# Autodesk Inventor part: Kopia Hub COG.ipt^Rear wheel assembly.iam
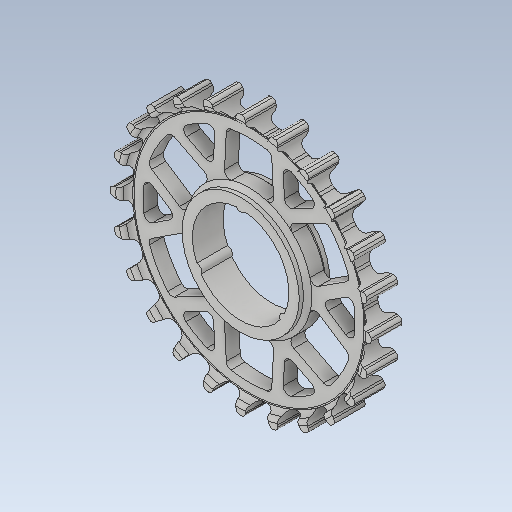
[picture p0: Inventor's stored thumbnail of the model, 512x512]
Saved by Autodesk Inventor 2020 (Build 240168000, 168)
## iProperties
Created: 2017-09
Part Number: Kopia Hub COG.ipt^Rear wheel assembly.iam
Material: Ogólny
Document SubType Name: Modeling
Designer: Tomasz
Density: 1 g/cm^3
Appearance: Domyślna
Sending System: SolidWorks 2017
Last Author: Tomasz
Last Saved: 2017-09-11
Author: Tomasz
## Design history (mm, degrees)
feature "Hub COG.ipt"
node "Bryła1"
